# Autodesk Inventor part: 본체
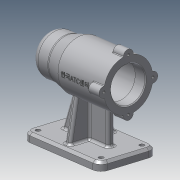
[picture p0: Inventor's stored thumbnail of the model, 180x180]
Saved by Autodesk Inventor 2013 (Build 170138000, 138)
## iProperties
Created: 2019-07
Part Number: 본체
Material: 알루미늄 6061
Document SubType Name: Modeling
Designer: 19
Density: 2.71 g/cm^3
Mass: 646.378 g
Surface Area: 663.133 cm^2
Volume: 238.516 cm^3
Author: 19
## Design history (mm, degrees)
sketch "스케치3"
  geometry: L1 (-56, 0)-(56, 0); L2 (-56, 0)-(-56, 25); L3 (-56, 25)-(-31, 25); L4 (-31, 25)-(-11, 30); L5 (-11, 30)-(56, 30); L6 (56, 30)-(56, 0); 2 further points
  constraints: 12 end point, 2 parallel, 2 perpendicular, 1 coincident, 1 horizontal, 1 midpoint
  dimensions: "d7" = 112 distance of L1.start L1.end; "d9" = 60 diameter of L5 L1; "d10" = 45 horizontal distance of L2.end L4.end; "d11" = 25 distance of L2.end L3.end; "d12" = 50 diameter of L3 L1
revolve "회전1" sketch "스케치3" stored, may be unused: angle "d13" = 90 deg
sketch "스케치13"
  geometry: L1 (0, 0)-(0, 30); C1 r 6 at (0, 30)
  constraints: 2 end point, 1 centre point, 1 coincident, 1 vertical, 1 vertical alignment, 1 other
  dimensions: "d52" = 12 diameter of C1
extrude "돌출5" join sketch "스케치13" distance "d53" = 16; taper "d54" = 0 deg
sketch "스케치15"
  geometry: L1 (56, 6)-(56, -6) reference; L2 (56, 0)-(-50, 0); L3 (56, 5.97)-(56, 29.4) reference; L4 (56, 21)-(41, 21); L5 (41, 21)-(41, 24); L6 (41, 24)-(-13, 24); L7 (-13, 24)-(-13, 21); L8 (-13, 21)-(-25, 21); L9 (-25, 21)-(-25, 17.5); L10 (-25, 17.5)-(-43, 17.5); L11 (-43, 17.5)-(-43, 16); L12 (-43, 16)-(-47, 16); L13 (-47, 16)-(-47, 10.5); L14 (-47, 10.5)-(-50, 10.5); L15 (-50, 10.5)-(-50, 0); L16 (56, 21)-(56, 0); 2 further points
  constraints: 28 end point, 10 parallel, 3 perpendicular, 1 collinear, 1 midpoint, 1 point on line
  dimensions: "d62" = 54 distance between parallel lines of L5 L7; "d64" = 48 diameter of L6 L2; "d65" = 15 distance from line of L4.start L5; "d66" = 42 diameter of L4 L2; "d67" = 42 diameter of L8 L2; "d68" = 12 distance of L7.end L8.end; "d69" = 35 diameter of L10 L2; "d70" = 18 distance from line of L9.end L11; "d71" = 4 distance of L11.end L12.end; "d73" = 3 distance from line of L13.end L15; "d74" = 32 diameter of L12 L2; "d75" = 21 diameter of L14 L2
revolve "회전3" sketch "스케치15" stored, may be unused: angle "d76" = 90 deg
node "작업 평면3"
sketch "스케치16"
  geometry: L1 (56, 35)-(-56, 35); L2 (-56, 35)-(-56, -35); L3 (-56, -35)-(56, -35); L4 (56, -35)-(56, 35); L5 (56, 35)-(-56, -35); L6 (-56, 35)-(56, -35); 1 further point
  constraints: 12 end point, 2 midpoint, 2 parallel, 1 horizontal, 1 perpendicular
  dimensions: "d78" = 112 distance of L3.end L2.end; "d79" = 70 distance of L2.end L1.end
extrude "돌출6" join sketch "스케치16" distance "d80" = 10; taper "d81" = 0 deg
sketch "스케치17"
  geometry: L1 (-70, -35)-(-70, 35) reference; L2 (-22.666, 19.654)-(-70, 28); L3 (-22.666, -19.654)-(-70, -28); A1 r 30 centre (0, 0) between (-22.666, 19.654) and (-22.666, -19.654) reference; 1 further point
  constraints: 4 end point, 2 point on circle, 2 point on line
  dimensions: "d82" = 100 deg angle of L1 L2; "d83" = 100 deg angle of L1 L3; "d84" = 7 distance of L1.end L2.end; "d85" = 7 distance of L1.start L3.end
extrude "돌출7" join sketch "스케치17" stored distance "d86" = 8; taper "d87" = 0 deg
sketch "스케치18"
  geometry: L1 (56, -29.4)-(56, -36) reference; L2 (56, -36)-(40, -36) reference; L3 (-56, -25)-(-31, -25) reference; L4 (-31, -25)-(-11, -30) reference; L5 (56, -70)-(-56, -70) reference; L6 (-11, -30)-(40, -30) reference; L7 (31, -30)-(31, -70); L8 (-20.57, -27.607)-(-36, -70); 1 further point
  constraints: 4 end point, 4 point on line, 1 perpendicular
  dimensions: "d88" = 20 distance of L5.end L8.end; "d89" = 110 deg angle of L5 L8; "d90" = 25 distance from line of L5.start L7
extrude "돌출8" join sketch "스케치18" stored distance "d91" = 8; taper "d92" = 0 deg
fillet "모깎기1" dims "d93" = 10
chamfer "모따기2" distance "d98" = 1; stored, may be unused: second distance "d99" = 2, angle "d100" = 45 deg
fillet "모깎기3" dims "d101" = 0.3
fillet "모깎기4" dims "d102" = 3
fillet "모깎기5" dims "d103" = 3
sketch "스케치19"
  geometry: A1 r 6 centre (0, 0) between (5.97, -0.6) and (-5.97, -0.6) reference; A2 r 6 centre (-30, -30) between (-29.4, -24.03) and (-29.4, -35.97) reference; A3 r 6 centre (0, -60) between (-5.97, -59.4) and (5.97, -59.4) reference; A4 r 6 centre (30, -30) between (29.4, -35.97) and (29.4, -24.03) reference; 4 further points
  constraints: 4 coincident
hole "구멍1" sketch "스케치19" at (0, 0), (30, -30), (0, -60), (-30, -30) diameter "d104" = 3.242; stored, may be unused: countersink angle "d108" = 90 deg, drill point angle "d110" = 118 deg; dims "d105" = 8, "d106" = 4, "d107" = 2, "d109" = 11
fillet "모깎기6" dims "d111" = 10
sketch "스케치20"
  geometry: C1 r 3 at (-46, 25); C2 r 3 at (-46, -25); C3 r 3 at (46, -25); C4 r 3 at (46, 25); A1 r 10 centre (-46, 25) between (-46, 35) and (-56, 25) reference; A2 r 10 centre (-46, -25) between (-56, -25) and (-46, -35) reference; A3 r 10 centre (46, -25) between (46, -35) and (56, -25) reference; A4 r 10 centre (46, 25) between (56, 25) and (46, 35) reference; 1 further point
  constraints: 4 centre point, 4 coincident
  dimensions: "d112" = 6 diameter of C1; "d113" = 6 diameter of C2; "d114" = 6 diameter of C3; "d115" = 6 diameter of C4
extrude "돌출9" cut sketch "스케치20" stored distance "d116" = 8; taper "d117" = 0 deg
fillet "모깎기10" dims "d121" = 3
fillet "모깎기11" dims "d122" = 3
fillet "모깎기12" dims "d123" = 3
fillet "모깎기13" dims "d124" = 1
fillet "모깎기14" dims "d125" = 1
fillet "모깎기15" dims "d126" = 1
chamfer "모따기3" distance "d127" = 1; stored, may be unused: second distance "d128" = 2, angle "d129" = 45 deg
chamfer "모따기5" distance "d133" = 3; stored, may be unused: second distance "d134" = 2, angle "d135" = 45 deg
node "작업 평면4"
sketch "스케치21"
  geometry: L1 (56, 6.771)-(56, 29.226) reference; 2 further points
  constraints: 1 horizontal alignment, 1 other
  dimensions: "d137" = 42 distance from line of point (14, 0) L1
feature "엠보싱1" sketch "스케치21" dims "d138" = 0.5, "d139" = 0
node "솔리드2"
pattern_circular "원형 패턴2" dims angle "d56" = 360 deg
